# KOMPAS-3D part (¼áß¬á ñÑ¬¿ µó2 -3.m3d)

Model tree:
1. Эскиз:1
2. Операция выдавливания:1
     Толщина стенки 1 = 7; Толщина стенки 2 = 6; Расстояние 1 = 0.6
3. Эскиз:2
4. Вырезать элемент выдавливания:1
     Толщина стенки 2 = 15; Расстояние 1 = 10
5. Эскиз:3
6. Вырезать элемент выдавливания:2
     Толщина стенки 1 = 8; Толщина стенки 2 = 15; Расстояние 1 = 10
7. Эскиз:4
8. Вырезать элемент выдавливания:3
     Толщина стенки 1 = 7; Расстояние 1 = 10
9. Эскиз:6
10. Вырезать элемент выдавливания:5
     Толщина стенки 1 = 7; Расстояние 1 = 10
